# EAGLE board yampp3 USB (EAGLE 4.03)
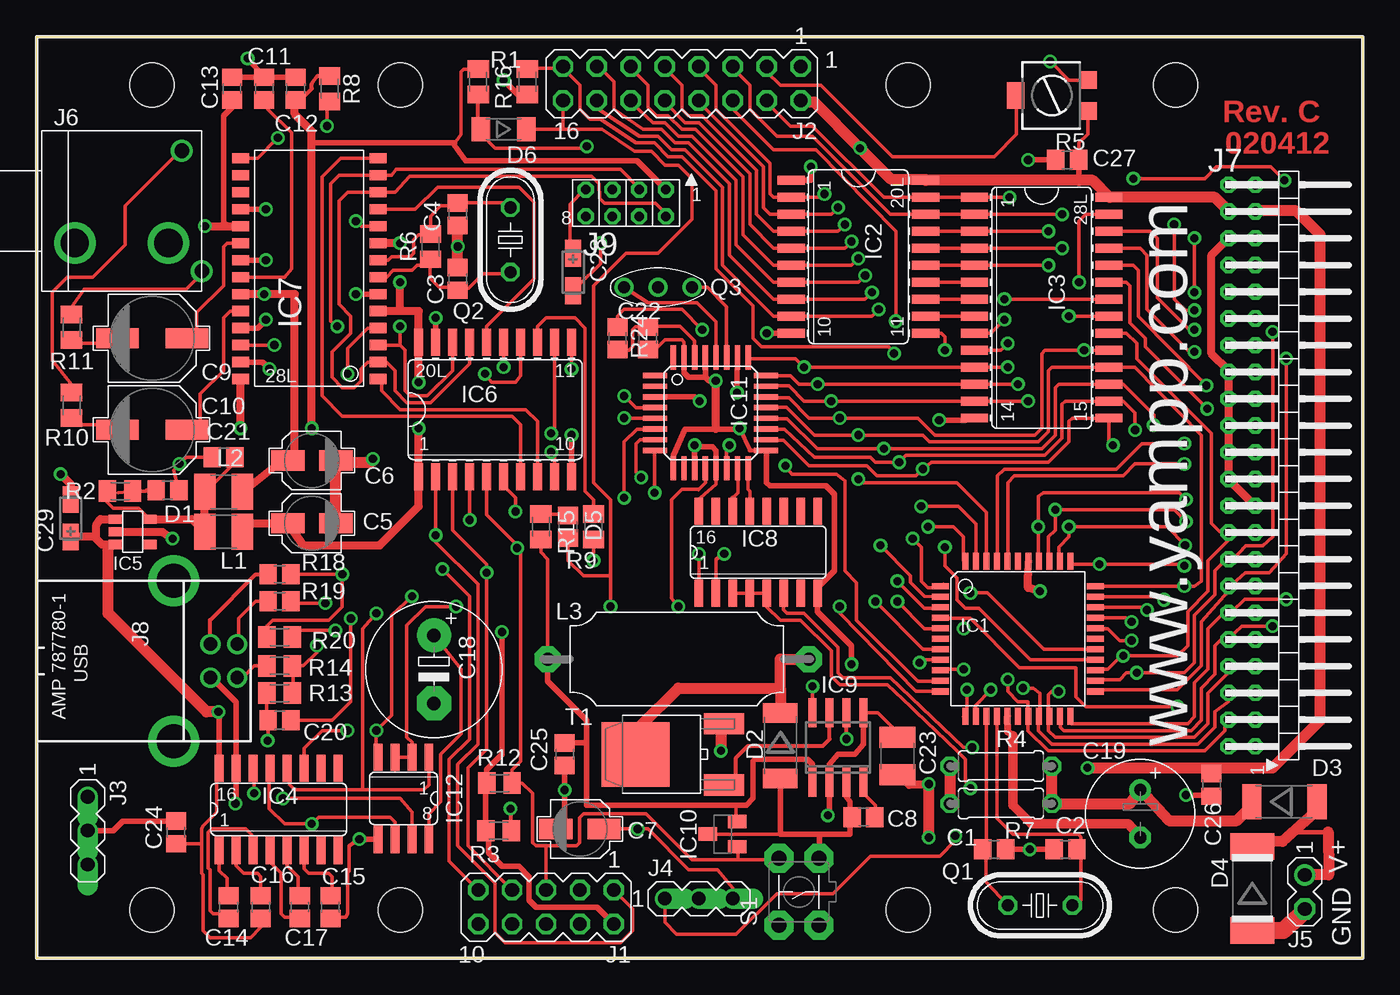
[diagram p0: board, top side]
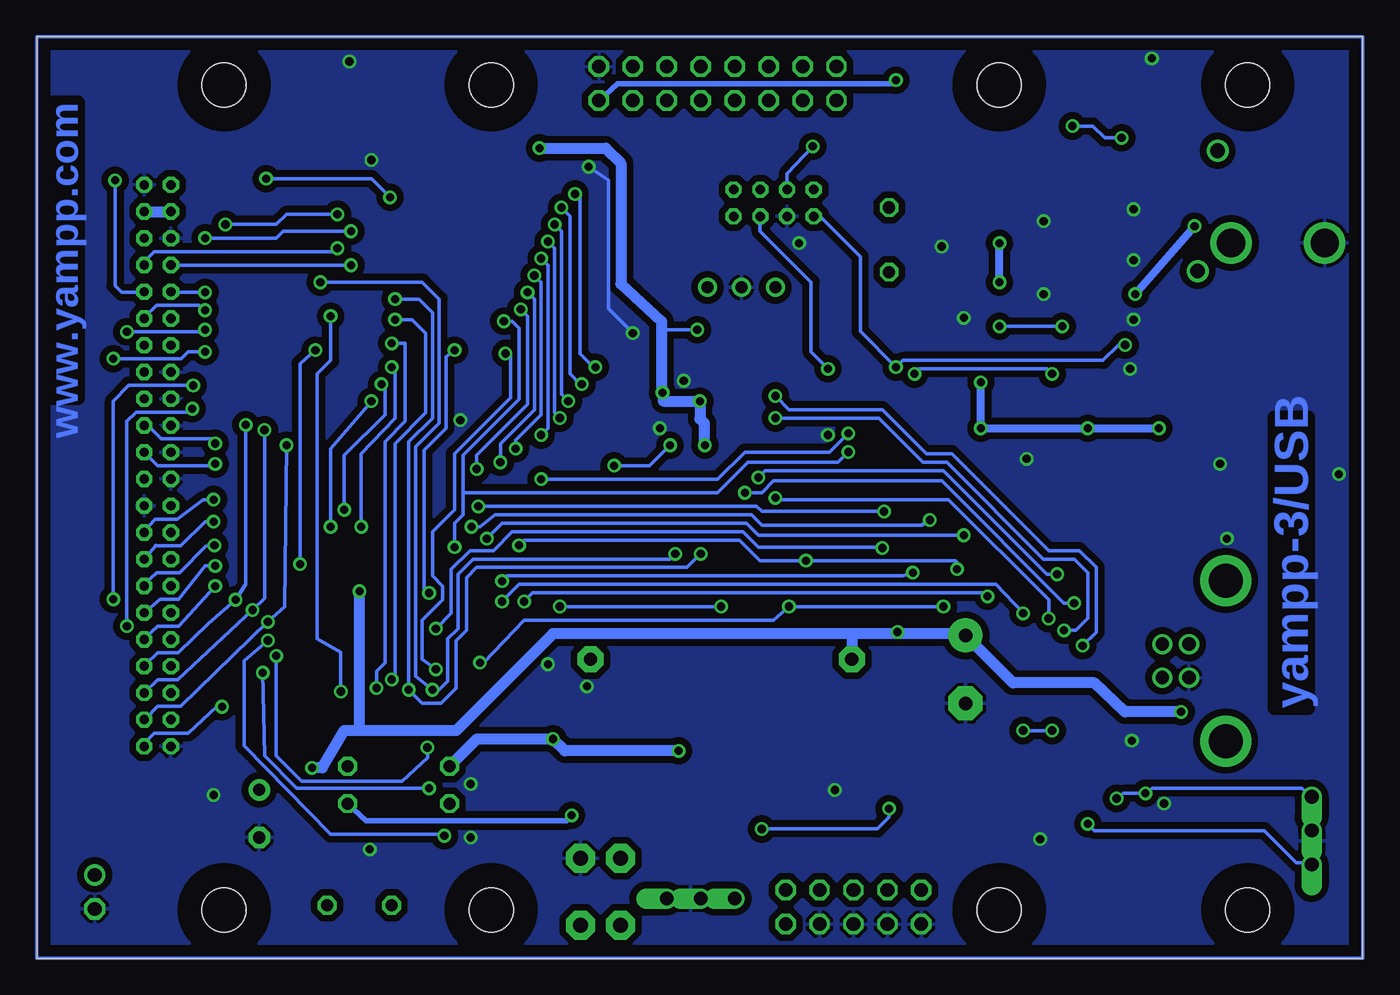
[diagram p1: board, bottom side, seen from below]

Size 99.2 x 68.9 mm. Coordinates in mm from the lower left corner, seen from the top.
Outline: 0,0 0,68.9 99.2,68.9 99.2,0 0,0
Copper layers used: Top, Bottom
Holes 3.3 mm at 85.2,3.6 65.2,3.6 27.2,3.6 8.6,3.6 85.2,65.3 65.2,65.3 27.2,65.3 8.6,65.3
tRestrict: area 6.9,63.6 to 10.3,67; area 25.5,63.6 to 28.9,67; area 63.5,63.6 to 66.9,67; area 83.5,63.6 to 86.9,67; area 83.5,1.9 to 86.9,5.3; area 63.5,1.9 to 66.9,5.3; area 25.5,1.9 to 28.9,5.3; area 6.9,1.9 to 10.3,5.3
bRestrict: area 6.9,63.6 to 10.3,67; area 25.5,63.6 to 28.9,67; area 63.5,63.6 to 66.9,67; area 83.5,63.6 to 86.9,67; area 83.5,1.9 to 86.9,5.3; area 63.5,1.9 to 66.9,5.3; area 25.5,1.9 to 28.9,5.3; area 6.9,1.9 to 10.3,5.3

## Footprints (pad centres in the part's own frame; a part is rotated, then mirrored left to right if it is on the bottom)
C0805 = smd 1.3 x 1.5: 1 -0.85,0; 2 0.85,0
ELNA_RV2_4 = smd 1.5 x 2.5: + 0,1.8; - 0,-1.8
ELNA_RV2_63 = smd 1.5 x 3.2: + 0,2.6; - 0,-2.6
E5-10,5 = drill 1.016 pad 2.54 round: + -2.54,0 | drill 1.016 pad 2.54 octagon: - 2.54,0
E3,5-8 = drill 0.9 pad 1.6 round: + -1.778,0 | drill 0.9 pad 1.6 octagon: - 1.778,0
C3225 = smd 1.6 x 2.7: 1 -1.4,0; 2 1.4,0
CT3216 = smd 2 x 1.2: + -1.4,0; - 1.4,0
LED0805 = smd 1.3 x 1.5: 1 -0.85,0; 2 0.85,0
SOD87 = smd 1.45 x 2.6: A 2.445,0; K -2.445,0
SOD87' = smd 1.45 x 2.6: 1 -2.445,0; 2 2.445,0
SOD15 = smd 2 x 3.3: A 3.145,0; K -3.145,0
SOD80 = smd 1.4 x 1.8: 1 -1.7,0; 2 1.7,0
TQFP44 = smd 1.27 x 0.457: 1 -5.791,3.937; 2 -5.791,3.15; 3 -5.791,2.362; 4 -5.791,1.575; 5 -5.791,0.787; 6 -5.791,0; 7 -5.791,-0.787; 8 -5.791,-1.575; 9 -5.791,-2.362; 10 -5.791,-3.15; 11 -5.791,-3.937; 23 5.791,-3.937; 24 5.791,-3.15; 25 5.791,-2.362; 26 5.791,-1.575; 27 5.791,-0.787; 28 5.791,0; 29 5.791,0.787; 30 5.791,1.575; 31 5.791,2.362; 32 5.791,3.15; 33 5.791,3.937 | smd 0.457 x 1.27: 12 -3.937,-5.791; 13 -3.15,-5.791; 14 -2.362,-5.791; 15 -1.575,-5.791; 16 -0.787,-5.791; 17 0,-5.791; 18 0.787,-5.791; 19 1.575,-5.791; 20 2.362,-5.791; 21 3.15,-5.791; 22 3.937,-5.791; 34 3.937,5.791; 35 3.15,5.791; 36 2.362,5.791; 37 1.575,5.791; 38 0.787,5.791; 39 0,5.791; 40 -0.787,5.791; 41 -1.575,5.791; 42 -2.362,5.791; 43 -3.15,5.791; 44 -3.937,5.791
SO20L = smd 0.66 x 2.032: 1 -5.715,-5.029; 2 -4.445,-5.029; 3 -3.175,-5.029; 4 -1.905,-5.029; 5 -0.635,-5.029; 6 0.635,-5.029; 7 1.905,-5.029; 8 3.175,-5.029; 9 4.445,-5.029; 10 5.715,-5.029; 11 5.715,5.029; 12 4.445,5.029; 13 3.175,5.029; 14 1.905,5.029; 15 0.635,5.029; 16 -0.635,5.029; 17 -1.905,5.029; 18 -3.175,5.029; 19 -4.445,5.029; 20 -5.715,5.029
SO28L = smd 0.66 x 2.032: 1 -8.255,-5.029; 2 -6.985,-5.029; 3 -5.715,-5.029; 4 -4.445,-5.029; 5 -3.175,-5.029; 6 -1.905,-5.029; 7 -0.635,-5.029; 8 0.635,-5.029; 9 1.905,-5.029; 10 3.175,-5.029; 11 4.445,-5.029; 12 5.715,-5.029; 13 6.985,-5.029; 14 8.255,-5.029; 15 8.255,5.029; 16 6.985,5.029; 17 5.715,5.029; 18 4.445,5.029; 19 3.175,5.029; 20 1.905,5.029; 21 0.635,5.029; 22 -0.635,5.029; 23 -1.905,5.029; 24 -3.175,5.029; 25 -4.445,5.029; 26 -5.715,5.029; 27 -6.985,5.029; 28 -8.255,5.029
SO16 = smd 0.66 x 2.032: 1 -4.445,-3.073; 2 -3.175,-3.073; 3 -1.905,-3.073; 4 -0.635,-3.073; 5 0.635,-3.073; 6 1.905,-3.073; 7 3.175,-3.073; 8 4.445,-3.073; 9 4.445,3.073; 10 3.175,3.073; 11 1.905,3.073; 12 0.635,3.073; 13 -0.635,3.073; 14 -1.905,3.073; 15 -3.175,3.073; 16 -4.445,3.073
M5 = smd 0.686 x 0.991: 1 -0.953,-1.283; 2 0,-1.283; 3 0.953,-1.283; 4 0.953,1.308; 5 -0.953,1.308
SOIC-28 = smd 0.762 x 1.27: 1 -7.62,-5.207; 2 -6.35,-5.207; 3 -5.08,-5.207; 4 -3.81,-5.207; 5 -2.54,-5.207; 6 -1.27,-5.207; 7 0,-5.207; 8 1.27,-5.207; 9 2.54,-5.207; 10 3.81,-5.207; 11 5.08,-5.207; 12 6.35,-5.207; 13 7.62,-5.207; 14 8.89,-5.207; 15 8.89,5.08; 16 7.62,5.08; 17 6.35,5.08; 18 5.08,5.08; 19 3.81,5.08; 20 2.54,5.08; 21 1.27,5.08; 22 0,5.08; 23 -1.27,5.08; 24 -2.54,5.08; 25 -3.81,5.08; 26 -5.08,5.08; 27 -6.35,5.08; 28 -7.62,5.08
SO8 = smd 0.6 x 2.2: 1 -1.905,-2.6; 2 -0.635,-2.6; 3 0.635,-2.6; 4 1.905,-2.6; 5 1.905,2.6; 6 0.635,2.6; 7 -0.635,2.6; 8 -1.905,2.6
SOT23 = smd 1 x 1.4: 1 -0.95,-1.1; 2 0.95,-1.1; 3 0,1.1
QFP32 = smd 0.4 x 1.8: 1 -2.8,-4.15; 2 -2,-4.15; 3 -1.2,-4.15; 4 -0.4,-4.15; 5 0.4,-4.15; 6 1.2,-4.15; 7 2,-4.15; 8 2.8,-4.15; 17 2.8,4.15; 18 2,4.15; 19 1.2,4.15; 20 0.4,4.15; 21 -0.4,4.15; 22 -1.2,4.15; 23 -2,4.15; 24 -2.8,4.15 | smd 1.8 x 0.4: 9 4.15,-2.8; 10 4.15,-2; 11 4.15,-1.2; 12 4.15,-0.4; 13 4.15,0.4; 14 4.15,1.2; 15 4.15,2; 16 4.15,2.8; 25 -4.15,2.8; 26 -4.15,2; 27 -4.15,1.2; 28 -4.15,0.4; 29 -4.15,-0.4; 30 -4.15,-1.2; 31 -4.15,-2; 32 -4.15,-2.8
SO08 = smd 0.66 x 2.032: 1 -1.905,-3.073; 2 -0.635,-3.073; 3 0.635,-3.073; 4 1.905,-3.073; 5 1.905,3.073; 6 0.635,3.073; 7 -0.635,3.073; 8 -1.905,3.073
MA05-2 = drill 1.016 octagon: 1 -5.08,-1.27; 2 -5.08,1.27; 3 -2.54,-1.27; 4 -2.54,1.27; 5 0,-1.27; 6 0,1.27; 7 2.54,-1.27; 8 2.54,1.27; 9 5.08,-1.27; 10 5.08,1.27
MA08-2 = drill 1.016 octagon: 1 -8.89,-1.27; 2 -8.89,1.27; 3 -6.35,-1.27; 4 -6.35,1.27; 5 -3.81,-1.27; 6 -3.81,1.27; 7 -1.27,-1.27; 8 -1.27,1.27; 9 1.27,-1.27; 10 1.27,1.27; 11 3.81,-1.27; 12 3.81,1.27; 13 6.35,-1.27; 14 6.35,1.27; 15 8.89,-1.27; 16 8.89,1.27
MA03-1 = drill 1.016 offset: 1 -2.54,0; 2 0,0; 3 2.54,0
MA02-1 = drill 1.016 pad 1.6 round: 1 -1.27,0 | drill 1.016 pad 1.6 octagon: 2 1.27,0
JACKSW = drill 2.1 round: 1 2.4,-3.5; 3 2.4,3.5 | drill 1.1 round: 2 4.5,6; 4 -4.5,4.5
CON40L-2W = drill 0.7 pad 1.118 octagon: 1 21,1; 2 21,-1; 3 19,1; 4 19,-1; 5 17,1; 6 17,-1; 7 15,1; 8 15,-1; 9 13,1; 10 13,-1; 11 11,1; 12 11,-1; 13 9,1; 14 9,-1; 15 7,1; 16 7,-1; 17 5,1; 18 5,-1; 19 3,1; 20 3,-1; 21 1,1; 22 1,-1; 23 -1,1; 24 -1,-1; 25 -3,1; 26 -3,-1; 27 -5,1; 28 -5,-1; 29 -7,1; 30 -7,-1; 31 -9,1; 32 -9,-1; 33 -11,1; 34 -11,-1; 35 -13,1; 36 -13,-1; 37 -15,1; 38 -15,-1; 39 -17,1; 40 -17,-1; 41 -19,1; 42 -19,-1; 43 -21,1; 44 -21,-1
USB-B = drill 1 round: 1 1.25,14.99; 2 -1.25,14.99; 3 -1.25,12.99; 4 1.25,12.99 | drill 2.54 pad 3.81 round: P$1 -6,10.25; P$2 6,10.25
CON8-2 = drill 0.7 pad 1.118 octagon: 1 3,0.98; 2 3,-1.02; 3 1,0.98; 4 1,-1.02; 5 -1,0.98; 6 -1,-1.02; 7 -3,0.98; 8 -3,-1.02
L1210 = smd 1.6 x 2.7: 1 -1.4,0; 2 1.4,0
HM50 = drill 1 pad 1.93 octagon: P$1 -9.89,0; P$2 9.66,0
HC49U-V = drill 0.9 octagon: 1 -2.413,0; 2 2.413,0
MURATA_CST = drill 0.9 round: 1 -2.54,0; 2 0,0; 3 2.54,0
M0805 = smd 1.3 x 1.6: 1 -0.95,0; 2 0.95,0
0207/7 = drill 0.9 octagon: 1 -3.81,0; 2 3.81,0
23B = smd 1.3 x 1.3: 1 -1.15,-2.7; 3 1.15,-2.7 | smd 2 x 1.3: 2 0,2.7
R0805 = smd 1.3 x 1.5: 1 -0.85,0; 2 0.85,0
ALPS_45 = drill 1.118 pad 2.159 octagon: 1 -2.49,1.5; 2 2.51,1.5; 3 -2.49,-1.5; 4 2.51,-1.5
DPAK_369A_2 = smd 5.08 x 4.826: D -3.861,0 | smd 2.997 x 1.6: G 2.769,-2.286; S 2.769,2.286

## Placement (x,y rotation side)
C1  33pF  [C0805]  71.63,8.13 0 top
C2  33pF  [C0805]  76.96,8.13 180 top
C3  33pF  [C0805]  31.5,50.8 270 top
C4  33pF  [C0805]  31.5,55.63 90 top
C5  10uF/16  [ELNA_RV2_4]  20.57,32.51 90 top
C6  10uF/16  [ELNA_RV2_4]  20.57,37.21 90 top
C7  10uF/16  [ELNA_RV2_4]  40.64,9.65 270 top
C8  100nF  [C0805]  61.85,10.54 0 top
C9  100uF/10  [ELNA_RV2_63]  8.64,46.35 270 top
C10  100uF/10  [ELNA_RV2_63]  8.64,39.5 270 top
C11  100nF  [C0805]  17.02,65.02 90 top
C12  100nF  [C0805]  19.37,65.02 90 top
C13  100nF  [C0805]  14.61,65.02 90 top
C14  100nF  [C0805]  16.76,3.81 90 top
C15  100nF  [C0805]  21.97,3.81 270 top
C16  100nF  [C0805]  14.35,3.81 270 top
C17  100nF  [C0805]  19.68,3.81 90 top
C18  220uF  [E5-10,5]  29.72,21.59 270 top
C19  47uF  [E3,5-8]  82.55,10.79 270 top
C20  100nF  [C0805]  18.16,17.78 0 top
C21  100nF  [C0805]  13.97,37.47 0 top
C22  100nF  [C0805]  45.72,46.35 90 top
C23  470nF  [C3225]  64.39,15.11 90 top
C24  100nF  [C0805]  10.41,9.4 270 top
C25  100nF  [C0805]  39.5,15.24 90 top
C26  100nF  [C0805]  87.88,12.95 90 top
C27  100nF  [C0805]  77.09,59.69 0 top
C28  1uF/16  [CT3216]  40.13,51.31 270 top
C29  1uF/16  [CT3216]  2.54,32.89 90 top
D1  [LED0805]  9.78,34.99 0 top
D2  PRLL5818  [SOD87]  55.63,15.88 270 top
D3  LL4004  [SOD87']  93.34,11.68 0 top
D4  SM15T15A  [SOD15]  90.93,5.21 270 top
D5  [LED0805]  39.75,32.26 270 top
D6  BAS32  [SOD80]  34.92,61.98 180 top
IC1  ATmega161  [TQFP44]  73.41,23.88 0 top
IC2  74HC573  [SO20L]  61.47,52.45 270 top
IC3  62256  [SO28L]  75.18,48.64 270 top
IC4  MAX202CSE  [SO16]  18.1,11.11 0 top
IC5  LP2980  [M5]  7.18,31.88 270 top
IC6  74LVC245  [SO20L]  34.29,41.02 0 top
IC7  VS1001  [SOIC-28]  20.32,50.93 90 top
IC8  74HC138D  [SO16]  53.98,30.35 0 top
IC9  MAX1626ESA  [SO8]  59.94,15.75 0 top
IC10  DS1813R  [SOT23]  51.31,9.27 90 top
IC11  FT8U245BM  [QFP32]  50.42,40.77 270 top
IC12  MAX481CSA  [SO08]  27.43,11.94 180 top
J1  PROG  [MA05-2]  38.1,3.81 180 top
J2  DISPLAY  [MA08-2]  48.26,65.41 180 top
J3  RS-232  [MA03-1]  3.81,9.53 270 top
J4  IR  [MA03-1]  49.53,4.45 0 top
J5  POWER  [MA02-1]  94.87,4.95 270 top
J6  Headphones  [JACKSW]  6.35,55.88 270 top
J7  ATA_IF  [CON40L-2W]  90.17,36.83 270 top
J8  USB  [USB-B]  0,22.23 270 top
J9  NOKIA LCD  [CON8-2]  44.07,56.49 0 top
L1  10u  [L1210]  13.97,31.88 0 top
L2  10u  [L1210]  13.97,34.86 0 top
L3  22uH  [HM50]  47.88,22.35 180 top
Q1  7.3728 MHz  [HC49U-V]  75.06,3.94 180 top
Q2  12.288 MHz  [HC49U-V]  35.43,53.72 90 top
Q3  6MHz  [MURATA_CST]  46.48,50.16 180 top
R1  10k  [M0805]  36.7,65.53 270 top
R2  470  [M0805]  6.22,34.92 180 top
R3  47  [M0805]  34.54,9.53 180 top
R4  0.1R  [0207/7]  72.14,14.35 0 top
R5  5k  [23B]  75.95,64.52 90 top
R6  1M  [M0805]  29.46,53.21 90 top
R7  0.1R  [0207/7]  72.14,11.56 0 top
R8  10k  [M0805]  21.91,65.02 270 top
R9  4k7  [M0805]  41.66,32.26 90 top
R10  15  [M0805]  2.6,41.34 90 top
R11  15  [M0805]  2.6,47.18 90 top
R12  10k  [M0805]  34.61,13.08 180 top
R13  10k  [M0805]  18.16,19.81 0 top
R14  4k7  [M0805]  18.16,21.84 180 top
R15  1k  [M0805]  37.72,32.26 270 top
R16  4k7  [M0805]  33.02,65.53 270 top
R18  27  [R0805]  18.16,28.7 180 top
R19  27  [R0805]  18.16,26.67 180 top
R20  1k5  [M0805]  18.16,24 180 top
R24  470  [R0805]  43.43,46.35 90 top
S1  RESET  [ALPS_45]  57.02,4.95 90 top
T1  MTD20P03HDL  [DPAK_369A_2]  48.64,15.24 0 top

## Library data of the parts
C1-C4 C8 C11-C29 L1 L2 R1-R4 R6-R16 R18-R20 R24 = rcl
C5-C7 C9 C10 D2 D4 IC9 IC11 J6 L3 Q3 R5 T1 = jesper
D1 D5 = led
D3 D6 = semicon-smd-ipc
IC1 = atmel
IC2 IC3 = 74XXSMD
IC4 IC12 = maxim
IC5 = LP2980
IC6 = 74XX
IC7 = VLSI
IC8 = 74xx-us
IC10 = dallas
J1-J4 = CON-LSTB
J5 = CON-LSTB@2
J7 J9 = ribcon2
J8 = con-amp
Q1 Q2 = crystal
S1 = key

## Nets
/DIOR: IC1.41 J7.25
/DIOW: IC1.40 J7.23
A0: IC2.19 IC3.1 J2.4 J7.35
A1: IC2.18 IC3.2 J2.5 J7.33
A2: IC2.17 IC3.3 J7.36
A3: IC2.16 IC3.4 J7.37
A4: IC2.15 IC3.5 J7.38
A5: IC2.14 IC3.6
A6: IC2.13 IC3.7
A7: IC2.12 IC3.8
A8: IC1.18 IC3.9 J7.4
A9: IC1.19 IC3.10 J7.6
A10: IC1.20 IC3.21 J7.8
A11: IC1.21 IC3.23 J7.10
A12: IC1.22 IC3.24 J7.12
A13: IC1.23 IC3.25 J7.14
A14: IC1.24 IC3.26 IC8.3 IC8.4 IC8.5 J7.16
A15: IC1.25 IC3.20 IC8.6 J7.18
AD0: IC1.37 IC2.2 IC3.11 IC11.25 J2.7 J7.17
AD1: IC1.36 IC2.3 IC3.12 IC11.24 J2.8 J7.15
AD2: IC1.35 IC2.4 IC3.13 IC11.23 J2.9 J7.13
AD3: IC1.34 IC2.5 IC3.19 IC11.22 J2.10 J7.11
AD4: IC1.33 IC2.6 IC3.18 IC11.21 J2.11 J7.9
AD5: IC1.32 IC2.7 IC3.17 IC11.20 J2.12 J7.7
AD6: IC1.31 IC2.8 IC3.16 IC11.19 J2.13 J7.5
AD7: IC1.30 IC2.9 IC3.15 IC11.18 J2.14 J7.3
ALE: IC1.27 IC2.11
BSYNC: IC1.43 IC6.6
DC_IN: D3.2 D4.K J5.1
DREQ: IC1.42 IC6.12
GND: C1.2 C2.2 C3.1 C4.1 C5.- C6.- C7.- C8.1 C11.2 C12.2 C13.2 C15.2 C18.- C19.- C20.1 C21.1 C22.1 C23.1 C24.1 C25.1 C26.1 C27.1 C28.- C29.- D1.2 D2.A D4.A IC1.16 IC2.1 IC2.10 IC3.14 IC4.15 IC5.2 IC6.10 IC6.19 IC7.6 IC7.10 IC7.18 IC7.21 IC7.25 IC7.27 IC8.8 IC9.3 IC9.8 IC10.3 IC11.9 IC11.17 IC11.29 IC11.31 IC12.5 J1.4 J1.6 J1.8 J1.10 J2.1 J3.2 J4.2 J5.2 J6.1 J7.2 J7.19 J7.22 J7.24 J7.26 J7.28 J7.30 J7.40 J7.43 J8.4 J9.6 Q3.2 R5.3 R13.1 S1.4
IR_IN: IC1.29 J4.1
KEYS: IC1.9 J2.15 R1.1
LCD_E: IC1.26 IC6.9 J2.6
LCD_E3: IC6.11 J9.4
LCD_NEG: C15.1 IC4.6
MISO: IC1.2 J1.9 R9.1
MOSI: IC1.1 IC6.2 J1.1
MOSI3: IC6.18 IC7.3 IC7.13 J9.3
MP3: IC1.44 IC6.4
N$1: IC7.15 R8.2
N$2: C11.1 IC7.22
N$3: C10.+ IC7.24
N$4: C9.+ IC7.20
N$5: D1.1 R2.1
N$6: D2.K L3.P$1 T1.D
N$7: C1.1 IC1.14 Q1.2
N$8: J6.2 R11.2
N$9: C9.- R11.1
N$10: C2.1 IC1.15 Q1.1
N$12: IC4.14 IC12.7 J3.1
N$13: C4.2 IC7.8 Q2.2 R6.2
N$14: C3.2 IC7.7 Q2.1 R6.1
N$16: IC4.13 IC12.6 J3.3
N$17: IC6.13 R9.2
N$18: C16.2 IC4.3
N$19: C10.- R10.1
N$20: C17.2 IC4.5
N$21: C17.1 IC4.4
N$22: C14.2 IC4.2
N$23: J6.4 R10.2
N$24: IC8.13 IC11.16
N$25: IC8.14 IC11.15
N$26: IC9.7 T1.G
N$27: J8.3 R18.2
N$28: IC9.6 R4.1 R7.1 T1.S
N$29: C19.+ C23.2 D3.1 IC9.2 IC9.5 R4.2 R7.2
N$30: IC11.4 R13.2 R14.1
N$31: IC11.7 R18.1 R20.2
N$34: J8.1 R14.2
N$35: IC6.16 IC7.11
N$36: C21.2 IC5.5 L1.1 L2.1 R2.2
N$37: IC6.14 IC7.4
N$38: IC6.7 IC7.14
N$39: IC6.8 IC7.1
N$40: IC11.8 R19.1
N$41: C8.2 IC9.4
N$42: C20.2 IC11.6
N$43: IC11.5 R20.1
N$44: J8.2 R19.2
N$45: C22.2 IC11.30 R24.1
N$49: C16.1 IC4.1
N$50: D5.1 R15.1
N$53: C7.+ J4.3 R3.1
N$54: IC11.27 Q3.1
N$55: IC11.28 Q3.3
RD: IC1.13 IC3.22 IC8.1
RST: IC1.4 IC6.5 IC10.1 J1.5 J7.1 R12.1 S1.2
RST3: IC6.15 IC7.26 J9.8
RX: IC1.5 IC4.12 IC12.1
RXF: IC1.11 IC11.12
SCF: D6.2 J9.5 R16.2
SCK: IC1.3 IC6.3 J1.7
SCK3: IC6.17 IC7.2 IC7.12 J9.2
TX: IC1.7 IC4.11 IC12.4
TX_ENABLE: D5.2 D6.1 IC1.8 IC12.2 IC12.3 J2.16
TXE: IC1.10 IC11.14
VCC: C14.1 C18.+ C24.2 C25.2 C26.2 C27.2 C29.+ IC1.38 IC2.20 IC3.28 IC4.16 IC5.1 IC5.3 IC8.16 IC9.1 IC10.2 IC11.3 IC11.11 IC11.13 IC11.26 IC12.8 J1.2 J2.2 J7.41 J7.42 L3.P$2 R1.2 R3.2 R5.1 R12.2 R15.2 R24.2
VCC/2 [power]: C6.+ C13.1 IC7.19 IC7.23 L2.2
VDD: C5.+ C12.1 IC6.1 IC6.20 IC7.5 IC7.9 IC7.28 J9.1 L1.2 R8.1 R16.1
VO: J2.3 R5.2
VOUT: C28.+ J9.7
WR: IC1.12 IC3.27 IC8.2

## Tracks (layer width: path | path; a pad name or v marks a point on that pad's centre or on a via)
/DIOR  (via drill 0.61)
  Top 0.254: v85.85,38.48 82.68,38.48 80.77,36.58 72.39,36.58 71.88,36.07 71.88,29.72 IC1.41
  Bottom 0.254: J7.25 90.88,39.83 89.89,38.84 86.08,38.84 86.11,38.73 v85.85,38.48
/DIOW  (via drill 0.61)
  Top 0.254: v85.85,36.96 82.17,36.96 81.28,36.07 73.15,36.07 72.64,35.56 72.64,29.72 72.62,29.69 IC1.40
  Bottom 0.254: J7.23 90.17,36.83 85.98,36.83 v85.85,36.96
A0  (via drill 0.61)
  Top 0.254: J2.4 54.61,64.01 56.39,62.23 58.04,62.23 63.37,56.9 IC2.19 IC3.1 v72.77,56.9 | v82.04,58.29 87.38,58.29 88.27,59.18 92.33,59.18 v93.34,58.17
  Bottom 0.254: v72.77,56.9 74.17,58.29 v82.04,58.29 | v93.34,58.17 93.34,50.29 92.84,49.78 | 92.84,49.78 91.19,49.81 J7.35 | 92.84,49.78 90.93,49.78
A1  (via drill 0.61)
  Top 0.254: 66.55,55.63 66.5,55.42 IC2.18 | 66.55,55.63 IC3.2 v76.71,55.63 | IC2.18 66.55,55.63 | IC2.18 63.88,55.63 58.04,61.47 55.37,61.47 53.34,63.5 53.34,65.28 52.07,66.55 J2.5 | v85.09,54.86 85.09,49.28 85.92,48.45 v86.61,48.45
  Bottom 0.254: v76.71,55.63 80.52,55.63 81.28,54.86 v85.09,54.86 | J7.33 91.17,47.77 91.19,47.75 91.19,47.88 90.23,48.83 87.06,48.83 v86.61,48.45
A2  (via drill 0.61)
  Top 0.254: IC2.17 IC3.3 v75.69,54.36 | v86.61,53.85 v86.61,49.78
  Bottom 0.254: v75.69,54.36 80.77,54.36 81.28,53.85 v86.61,53.85 | J7.36 89.17,49.8 89.15,49.78 v86.61,49.78
A3  (via drill 0.61)
  Top 0.254: 66.29,53.09 IC2.16 70.1,53.09 | 70.1,53.09 IC3.4 | 70.1,53.09 v76.71,53.09
  Bottom 0.254: J7.37 91.17,52.09 90.42,52.83 76.96,52.83 v76.71,53.09
A4  (via drill 0.61)
  Top 0.254: IC2.15 IC3.5 v75.69,51.82
  Bottom 0.254: J7.38 89.15,51.82 v75.69,51.82
A5
  Top 0.254: IC2.14 IC3.6
A6
  Top 0.254: IC2.13 IC3.7
A7
  Top 0.254: IC2.12 IC3.8
A8  (via drill 0.61)
  Top 0.254: 74.17,18.03 74.17,17.02 75.69,15.49 87.38,15.49 88.9,17.02 88.9,17.27 89,17.48 J7.4 | 74.17,18.03 74.17,18.06 IC1.18 74.19,18.06 74.17,18.03 | IC3.9 71.37,46.74 v72.39,47.75 | 74.17,18.03 74.17,19.18 73.41,19.18 72.64,19.94 v72.64,20.83
  Bottom 0.254: v72.39,47.75 71.12,47.75 70.1,46.74 70.1,40.77 72.39,38.48 72.39,21.08 v72.64,20.83
A9  (via drill 0.61)
  Top 0.254: IC3.10 72.14,45.47 v72.64,45.97 | v73.79,20.19 74.55,20.19 75.06,19.81 75.06,18.54 74.93,18.29 74.98,18.24 IC1.19 74.93,18.03 74.93,17.02 75.95,16 86.87,16 88.14,17.27 88.14,18.41 89.15,19.18 89.15,19.76 89.15,19.81 J7.6
  Bottom 0.254: v72.64,45.97 71.63,45.97 71.63,40.13 73.15,38.61 73.15,22.1 73.79,21.46 v73.79,20.19
A10  (via drill 0.61)
  Top 0.254: J7.8 89.16,21.84 89.15,21.34 87.63,19.81 87.63,17.53 86.61,16.51 76.2,16.51 75.69,17.02 75.69,18.01 IC1.20 75.69,18.16 75.69,19.68 75.95,19.94 v76.45,19.94 | 80.26,48.01 IC3.21 v77.22,48.01
  Bottom 0.254: v76.45,19.94 76.45,22.86 78.23,23.88 78.23,43.69 77.22,44.7 v77.22,48.01
A11  (via drill 0.61)
  Top 0.254: IC1.21 76.58,17.93 76.58,17.27 76.83,17.02 86.36,17.02 87.12,17.78 87.12,20.19 88.14,21.21 88.14,23.37 88.65,23.88 89.15,23.88 | 89.15,23.88 89.15,23.85 J7.10 | 89.15,23.88 90.17,24.83 v92.46,24.83 | IC3.23 81.53,50.55 81.79,50.29 81.79,47.5 82.93,46.35 82.93,45.72 v87.57,41.08
  Bottom 0.254: v92.46,24.83 92.46,40.13 91.76,40.83 87.95,40.83 v87.57,41.08
A12  (via drill 0.61)
  Top 0.254: IC1.22 77.39,17.53 86.11,17.53 86.61,18.03 86.61,20.57 87.63,21.59 87.63,24.64 88.9,25.91 | J7.12 89.15,25.85 89.15,25.91 88.9,25.91 | 88.9,25.91 89.41,25.91 90.4,26.84 v93.47,26.84 | IC3.24 82.04,51.82 82.42,51.44 82.42,48.01 v87.5,42.82
  Bottom 0.254: v93.47,26.84 93.47,41.66 92.33,42.85 v87.5,42.82
A13  (via drill 0.61)
  Top 0.254: IC1.23 79.32,20.07 85.34,20.07 87.12,21.84 87.12,25.15 89.15,27.43 89.15,27.69 | 89.3,27.83 J7.14 89.15,27.81 89.15,27.69 | IC3.25 82.55,53.09 83.06,52.58 83.06,48.51 86.23,45.34 v86.61,45.34 | v93.47,44.83 93.47,30.23 92.2,28.83 90.42,28.83 89.15,27.69
  Bottom 0.254: v86.61,45.34 87.88,45.34 88.39,44.83 v93.47,44.83
A14  (via drill 0.61)
  Top 0.254: IC1.24 79.3,20.83 81.03,20.83 81.53,21.34 v82.3,21.34 85.85,21.34 86.61,22.1 86.61,25.65 88.14,27.18 88.14,28.96 88.9,29.72 | J7.16 89.15,29.81 89.15,29.72 88.9,29.72 | 88.9,29.72 89.41,29.72 90.45,30.82 91.72,30.82 92.46,31.5 v92.46,46.84 | IC3.26 83.31,54.36 83.82,53.85 83.82,49.4 86.23,46.99 v86.61,46.99 | IC8.3 IC8.4 | IC8.4 53.31,27.66 53.34,27.69 | IC8.4 54.59,27.28 | 54.59,27.28 IC8.5 54.61,26.29 55.63,25.27 57.15,25.27 59.44,22.99 59.44,21.08 60.07,20.45 63.63,20.45 65.41,18.8 65.79,18.41 68.83,15.49 69.47,14.86 69.47,13.21 v69.85,12.7 | 54.59,27.28 54.61,27.69
  Bottom 0.254: v86.61,46.99 87,46.84 v92.46,46.84 | v69.85,12.7 79.76,12.7 82.17,15.11 v82.3,21.34
A15  (via drill 0.61)
  Top 0.254: IC1.25 79.27,21.59 80.14,21.59 81.15,22.61 v81.28,22.61 85.34,22.61 86.11,23.37 86.11,25.91 87.63,27.43 87.63,29.72 89.15,31.24 89.15,31.75 | 89.15,31.85 89.15,32 | 89.15,31.85 J7.18 | IC3.20 81.53,46.74 82.3,45.97 82.3,44.83 87.88,39.24 87.88,32.51 88.52,31.88 89.03,31.88 89.15,31.75 | 89.15,31.75 89.15,31.85 | IC8.6 55.88,26.04 56.13,25.78 57.4,25.78 59.94,23.24 59.94,21.34 60.33,20.95 63.88,20.95 69.34,15.75 v69.98,15.75
  Bottom 0.254: v69.98,15.75 69.98,14.99 71.88,13.21 79.38,13.21 81.28,15.11 v81.28,22.61
AD0  (via drill 0.61)
  Top 0.254: J2.7 49.53,66.55 50.8,65.28 50.8,63.5 54.86,59.44 54.86,57.15 55.12,56.9 IC2.2 58.55,56.9 v58.93,57.15 | v72.64,44.2 IC3.11 v57.4,44.2 56.77,44.83 53.21,44.83 53.2,44.97 53.2,44.96 53.22,44.96 IC11.25 | IC1.37 74.93,29.72 v74.93,32.26 74.93,34.54 75.31,34.8 85.47,34.8 v85.98,34.29
  Bottom 0.254: v58.93,57.15 58.8,57.15 58.55,56.9 58.55,45.21 57.53,44.2 v57.4,44.2 | v72.64,44.2 72.39,43.94 72.39,40.39 74.93,37.72 v74.93,32.26 | J7.17 91.17,31.86 91.19,31.88 90.36,32.83 88.71,32.83 86.74,34.29 v85.98,34.29
AD1  (via drill 0.61)
  Top 0.254: J2.8 49.53,64.01 54.36,59.18 54.36,56.13 54.86,55.63 IC2.3 59.44,55.63 v59.94,56.13 | 54.61,43.56 54.62,43.57 | 54.61,43.56 56.39,43.56 57.02,42.93 v58.42,42.93 IC3.12 v73.41,42.93 | IC1.36 75.72,29.72 75.69,29.72 75.69,31.5 76.2,32 v76.2,33.53 85.09,33.53 v85.98,32.64 | IC11.24 54.48,43.57 54.48,43.56 54.61,43.56
  Bottom 0.254: v59.94,56.13 59.31,55.5 59.31,43.69 58.55,42.93 v58.42,42.93 | v73.41,42.93 73.15,42.67 73.15,40.64 76.2,37.59 v76.2,33.53 | 90.29,30.84 J7.15 | v85.98,32.64 86.61,32.64 88.42,30.84 90.29,30.84 | 90.29,30.84 90.3,30.86
AD2  (via drill 0.61)
  Top 0.254: J2.9 46.99,66.55 48.26,65.28 48.26,63.5 48.77,62.99 49.78,62.99 53.85,58.93 53.85,55.63 55.12,54.36 IC2.4 59.94,54.36 v60.45,54.86 | 54.86,42.8 54.83,42.77 | 54.86,42.8 56.26,42.8 57.4,41.66 v59.44,41.66 IC3.13 v74.17,41.66 | IC1.35 76.5,29.72 76.45,29.72 76.45,30.73 77.22,31.5 v77.22,32.26 84.58,32.26 v85.92,30.86 | IC11.23 54.61,42.77 54.61,42.8 54.86,42.8
  Bottom 0.254: v60.45,54.86 59.94,54.36 59.94,42.16 v59.44,41.66 | v74.17,41.66 77.22,38.1 v77.22,32.26 | J7.13 91.17,27.96 90.23,28.83 88.52,28.83 86.55,30.8 v85.92,30.86
AD3  (via drill 0.61)
  Top 0.254: J2.10 46.99,64.01 48.51,62.48 49.53,62.48 53.34,58.67 53.34,54.86 55.12,53.09 IC2.5 60.45,53.09 v60.96,53.59 | IC3.19 v78.36,45.47 75.44,45.47 75.18,45.21 75.18,39.62 74.68,39.12 67.18,39.12 65.91,40.39 v60.07,40.39 57.78,40.39 56.26,41.91 54.99,41.91 54.86,42.04 54.86,41.97 54.68,41.97 54.61,41.97 | 77.27,29.67 77.22,29.72 | 77.27,29.67 IC1.34 | v85.85,29.34 85.6,29.46 v79.5,29.46 77.47,29.46 77.27,29.67 | IC11.22 54.61,41.97 | 54.61,41.97 54.61,42.04
  Bottom 0.254: v60.96,53.59 60.45,53.09 60.45,40.77 v60.07,40.39 | v78.36,45.47 79.5,44.45 v79.5,29.46 | J7.11 89.96,26.84 88.59,26.84 86.61,29.34 v85.85,29.34
AD4  (via drill 0.61)
  Top 0.254: J2.11 44.45,66.55 45.72,65.28 45.72,63.63 46.35,62.99 47.24,62.99 48.26,61.98 49.28,61.98 52.83,58.42 52.83,54.1 55.12,51.82 IC2.6 60.96,51.82 v61.47,52.32 | IC1.33 v85.85,27.81 86.61,27.81 87.12,28.19 87.12,39.12 82.17,44.2 IC3.18 75.95,44.2 75.69,43.94 75.69,39.37 74.93,38.61 66.8,38.61 66.29,39.12 v61.47,39.12 58.17,39.12 56.07,41.21 54.86,41.21 54.76,41.17 54.61,41.17 | IC11.21 54.61,41.17 | 54.61,41.17 54.61,41.15
  Bottom 0.254: 91.06,24 90.17,24.83 88.58,24.83 v85.85,27.81 | 91.06,24 91.19,23.88 | v61.47,52.32 60.96,51.82 60.96,39.62 v61.47,39.12 | J7.9 91.03,23.98 91.06,24
AD5  (via drill 0.61)
  Top 0.254: J2.12 44.45,64.01 46.1,62.48 46.99,62.48 48.01,61.47 49.02,61.47 52.32,58.17 52.32,53.34 55.12,50.55 IC2.7 61.47,50.55 v61.98,51.05 | IC1.32 83.72,27.03 v84.33,26.8 | v83.57,39.88 83.57,40.64 81.28,42.93 IC3.17 76.45,42.93 76.2,42.67 76.2,39.12 75.18,38.1 v63.37,38.1 58.42,38.1 56.13,40.32 54.61,40.32 54.62,40.4 54.48,40.4 54.48,40.37 IC11.20
  Bottom 0.254: 91.06,21.97 90.14,22.84 88.62,22.84 86.36,25.02 v84.33,26.8 83.57,27.94 v83.57,39.88 | 91.06,21.97 91.19,21.84 | v61.98,51.05 61.47,50.55 61.47,40.64 63.37,38.73 v63.37,38.1 | J7.7 91.03,21.95 91.06,21.97
AD6  (via drill 0.61)
  Top 0.254: J2.13 41.91,66.8 43.18,65.53 43.18,63.5 45.34,61.98 46.74,61.98 47.75,60.96 48.77,60.96 51.82,57.91 51.82,52.58 55.12,49.28 IC2.8 61.98,49.28 v62.48,49.78 | IC1.31 82.6,26.24 v83.06,26.04 | 54.55,39.56 54.62,39.51 | 54.55,39.56 55.94,39.56 58.17,37.47 62.36,37.47 62.74,37.08 v64.52,37.08 65.02,37.59 75.44,37.59 76.71,38.86 76.71,41.4 76.96,41.66 IC3.16 81.28,41.66 82.17,40.77 v82.17,39.5 | 54.61,39.57 54.61,39.56 54.55,39.56 | IC11.19 54.61,39.57 | 54.61,39.57 54.61,39.62
  Bottom 0.254: J7.5 91.19,19.81 | J7.5 | J7.5 90.17,20.83 88.65,20.83 v83.06,26.04 82.17,26.92 v82.17,39.5 | v62.48,49.78 61.98,49.28 61.98,41.02 64.52,38.48 v64.52,37.08
AD7  (via drill 0.61)
  Top 0.254: J2.14 41.91,64.01 42.04,63.88 42.04,63.5 45.09,61.47 46.48,61.47 47.5,60.45 48.51,60.45 51.31,57.66 51.31,51.82 55.12,48.01 IC2.9 62.48,48.01 v62.99,48.51 | IC1.30 81.48,25.45 v81.92,25.15 | 54.62,38.74 54.61,38.73 54.74,38.73 | 54.74,38.73 55.88,38.73 57.78,36.83 62.1,36.83 62.87,36.07 65.79,36.07 v66.29,36.58 66.93,37.08 75.69,37.08 77.22,38.61 77.22,40.13 77.47,40.39 IC3.15 80.21,38.66 v80.52,38.35 | IC11.18 54.74,38.77 54.74,38.73
  Bottom 0.254: 91.06,17.91 90.14,18.83 88.49,18.83 88.44,18.85 v81.92,25.15 80.64,26.29 v80.52,38.35 | 91.06,17.91 91.19,17.78 | v62.99,48.51 62.48,48.01 62.48,41.4 66.29,37.59 v66.29,36.58 | J7.3 91.03,17.88 91.06,17.91
ALE  (via drill 0.61)
  Top 0.254: IC1.27 75.34,23.09 71.12,27.3 v69.85,27.3 | IC2.11 67.69,46.74 67.94,46.48 v67.94,45.47
  Bottom 0.254: v69.85,27.3 70.23,27.56 70.23,37.97 68.58,39.62 68.58,44.96 v67.94,45.47
BSYNC  (via drill 0.61)
  Top 0.254: IC1.43 70.26,32.49 68.96,33.78 v66.17,33.78 | v35.81,33.4 35.81,34.42 34.92,35.31 IC6.6
  Bottom 0.254: v66.17,33.78 45.34,33.78 44.96,33.4 v35.81,33.4
DC_IN
  Top 0.356: 93.19,8.73 93.98,9.4 96.62,9.43
  Top 0.813: D3.2 95.76,11.68 95.76,11.81 95.63,11.94 | D4.K 90.93,8.64 91.19,8.76 93.19,8.73 95.63,10.92 95.63,11.94 | 95.63,11.94 95.76,12.06 | 96.62,9.43 96.65,6.22 J5.1
DREQ  (via drill 0.61)
  Top 0.254: IC1.42 71.04,33.35 68.83,35.56 61.72,35.56 v61.47,35.81 | v38.48,39.24 38.73,39.37 IC6.12
  Bottom 0.254: v38.48,39.24 39.88,37.85 46.23,37.85 48.26,35.81 v61.47,35.81
GND  (via drill 0.61)
  Top 0.254: C12.2 19.34,66.25 19.3,66.29 19.27,66.25 | v14.86,11.56 14.92,11.62 | 47.62,37.12 47.62,37.09 IC11.9 | v24.13,8.89 23.37,8.38 23.37,6.48 23.24,6.35 23.24,3.3 23.11,3.05 22.1,3.05 22.19,2.96 C15.2 | 89.15,35.81 J7.22 | J7.19 91.14,33.83 | J7.24 89.15,37.85 | J7.26 89.17,39.86 89.15,39.88 | J7.28 89.17,41.89 89.15,41.91 | 89.15,43.94 89.17,43.93 J7.30 | 89.17,53.86 J7.40 89.15,53.85 | 76.49,8.04 76.58,7.87 76.58,8.13 76.49,8.04 | 76.49,8.04 C2.2 | IC2.1 56.39,58.17 | 69.49,40.23 IC3.14 70.36,40.39 | 12.95,21.08 12.99,21.05 J8.4 | 25.53,8.13 IC12.5 25.53,8.89 | 58.42,27.69 58.42,27.43 IC8.8 | 54.62,37.97 54.61,37.97 | 60.58,12.06 IC9.3 | 64.26,13.97 64.39,13.84 C23.1 64.27,13.97 64.26,13.97 | 61.09,10.54 C8.1 60.83,10.54 | IC9.8 v58.04,20.32 | 64.26,13.97 64.52,13.97 | 58.55,7.49 S1.4 58.55,7.47 58.55,7.49 | R5.3 78.62,65.67 78.61,65.66 77.22,65.66 v75.82,67.06 | C7.- 38.86,9.65 39.5,10.29 | v17.27,16.26 17.31,16.3 C20.1 17.31,17.87 17.21,17.97 R13.1 | 58.55,7.49 58.55,7.46 S1.4 | IC7.10 24.26,54.74 v23.88,55.12 | IC11.9 47.62,36.58 | IC11.9 | IC6.10 40.01,37.59 39.95,37.64 | D1.2 10.25,36.49 v10.67,36.96 11.18,37.47 C21.1 | IC10.3 58.55,9.27 | IC11.31 48.42,46.07 48.26,46.23 46.99,46.23 46.23,45.47 45.72,45.47 C22.1 | C28.- 40.51,50.29 42.16,51.94 v42.16,53.47 | 91.27,57.83 91.19,57.78 91.06,57.85 J7.43 91.27,57.83
  Top 0.305: v52.58,39.62 53.35,37.97 IC11.17 | 47.62,37.09 47.62,37.59
  Top 0.406: 14.92,11.62 IC4.15 14.92,19.11 12.99,21.05 | v23.88,49.66 IC7.6 | IC6.19 v29.84,47.88 | v54.61,46.74 IC2.10 | v52.58,39.62 52.64,39.56 50.8,39.56 48.51,39.55 47.62,37.59 | IC11.17 54.62,37.97 | C1.2 v74.3,8.13 76.58,8.13 | v57.91,59.18 57.91,58.17 IC2.1 | v67.51,40.23 69.49,40.23 | IC6.10 v40.01,39.12 | v24.13,8.89 25.53,8.89 | 58.42,27.69 59.69,28.96 59.69,34.67 59.05,35.31 54.86,35.31 54.61,35.56 54.61,37.97 | 60.58,12.06 60.83,11.68 60.83,10.54 60.83,9.27 58.55,9.27 | 58.55,9.27 55.63,9.27 D2.A | 58.55,9.27 58.55,7.49 | v74.17,59.69 C27.1 | C26.1 88.35,12.19 v85.98,12.19 | 22.35,36.43 C6.- 22.5,37.08 | C5.- 22.35,32.41 | 25.02,37.08 v25.15,37.34 | 39.5,10.29 v39.5,12.57 C25.1 | v60.96,21.97 60.96,23.37 58.42,25.91 58.42,27.43 | C24.1 6.44,10.25 5.71,9.53 J3.2 | IC7.18 v17.14,56.01 | IC7.27 16.89,44.58 v17.4,44.07 | IC7.21 v17.14,52.2 | IC7.25 16.51,47.12 v17.14,47.75 | C13.2 14.57,65.87 | 14.57,65.87 C11.2 | 14.57,65.87 14.48,66.17 | C11.2 v15.77,67.28 | 19.52,65.87 19.27,66.25 | C11.2 19.52,65.87 | 19.52,65.87 19.43,66.29 | v50.8,43.18 50.29,43.18 50.04,43.43 | IC11.29 50.02,43.45 50.04,43.43 | IC11.31 48.42,43.78 48.77,43.43 50.04,43.43
  Top 0.508: 72.64,16.94 IC1.16
  Top 0.559: 73.03,16.64 72.64,16.94
  Top 0.61: IC5.2 9.4,31.88 v10.16,31.37 | 91.14,33.83 89.15,35.81 | J7.22 J7.24 J7.26 J7.28 J7.30 | 89.17,43.93 87.88,45.21 87.88,52.58 89.15,53.85 | 50.8,39.56 v50.8,43.18 | 64.26,13.97 65.28,12.95 66.67,12.95 v66.74,13.02 66.8,13.08 | C29.- 2.54,35.43 v1.78,36.2
  Top 0.711: 73.03,16.64 73.03,11.43 74.42,10.03 81.66,10.03 C19.-
  Top 0.813: 22.35,32.41 22.35,36.43 | 22.5,37.08 25.02,37.08 | v66.74,9.02 v66.74,13.02 | C4.1 v31.5,53.21 C3.1 | 94.87,3.56 J5.2
  Top 1.27: D4.A 93.25,2.06 94.87,3.56
  Bottom 0.254: v54.61,46.74 56.44,48.56 IC2.1 v57.91,59.18 | v74.3,8.13 74.17,8.13 | 89.15,16 89.15,15.85 J7.2 | 91.14,57.83 91.06,57.91 | J7.43 91.14,57.83 | 91.14,57.83 91.19,57.78
  Bottom 0.406: v74.17,59.69 74.04,59.69
  pour Bottom (isolate 0.508): -1.02,-0.89 -1.02,70.23 100.08,69.98 100.08,-1.02
IR_IN  (via drill 0.61)
  Top 0.254: J4.1 46.99,2.67 47.88,1.78 52.32,1.78 55.37,4.83 59.56,4.83 62.36,7.62 67.56,7.62 68.71,8.76 v68.71,9.14 | v81.92,23.75 81.03,23.75 80.14,24.64 79.25,24.64 79.22,24.66 IC1.29
  Bottom 0.254: v68.71,9.14 68.83,9.14 68.83,9.27 77.22,9.27 83.69,15.88 83.69,22.23 v81.92,23.75
KEYS  (via drill 0.61)
  Top 0.254: 39.37,66.55 J2.15 | 39.37,66.55 40.64,65.28 40.64,63.5 41.4,62.74 42.16,62.74 44.83,60.96 46.23,60.96 47.24,59.94 48.26,59.94 50.8,57.4 50.8,51.56 53.59,48.77 53.59,46.35 54.23,45.72 63.75,45.72 v64.14,45.21 | IC1.9 67.69,21.59 v69.34,21.59 | R1.1 36.45,66.42 36.58,66.55 39.37,66.55
  Bottom 0.254: v64.14,45.21 63.75,45.21 63.75,41.91 67.94,37.72 67.94,33.53 69.6,31.88 69.6,28.57 68.83,27.81 68.83,26.8 70.36,25.27 70.36,22.35 v69.34,21.59
LCD_E  (via drill 0.61)
  Top 0.254: J2.6 52.07,63.5 55.12,60.45 58.29,60.45 64.26,54.36 v64.26,47.62 | IC1.26 74.35,22.3 70.48,26.16 69.47,26.16 68.83,26.8 68.83,28.45 67.94,29.34 v67.94,30.73 | IC6.9 38.73,37.59 v38.48,37.85
  Bottom 0.254: v67.94,30.73 67.94,32.51 67.31,33.15 67.31,34.8 | 67.31,34.8 67.31,37.59 63.12,41.78 63.12,47.12 63.63,47.62 v64.26,47.62 | v38.48,37.85 39.24,37.08 45.97,37.08 48.26,34.8 67.31,34.8
LCD_E3  (via drill 0.61)
  Top 0.254: v40.01,44.07 IC6.11
  Bottom 0.254: v40.01,44.07 41.27,45.34 41.27,50.55 45.09,54.36 45.08,55.49 J9.4
LCD_NEG
  Top 0.254: IC4.6 20,6.67 20.32,6.35 21.84,6.35 22.1,6.1 22.1,4.57 22.19,4.66 C15.1
MISO  (via drill 0.61)
  Top 0.254: IC1.2 66.42,27.05 65.38,28.09 65.38,28.6 v63.12,30.86 | v41.66,29.72 R9.1 | 32.38,23.62 32.38,16.38 30.86,14.86 30.86,7.24 J1.9 | v30.35,29.08 32.38,27.05 32.38,23.62 | 32.38,23.62 32.38,23.75
  Bottom 0.254: v63.12,30.86 62.74,31.24 46.61,31.24 45.09,29.72 v41.66,29.72 30.48,29.72 30.35,29.59 v30.35,29.08
MOSI  (via drill 0.61)
  Top 0.254: IC6.2 v29.84,31.62 29.84,31.11 33.02,27.94 33.02,16 31.5,14.48 31.5,8.38 34.29,5.59 34.29,1.91 35.05,1.14 43.69,1.14 44.58,2.03 44.58,3.68 J1.1 | v65.53,31.37 66.17,30.73 66.17,28.19 66.67,27.69 67.56,27.69 67.69,27.81 | 67.69,27.81 67.82,27.94 | 67.69,27.81 IC1.1
  Bottom 0.254: v29.84,31.62 45.21,31.62 46.1,32.51 64.39,32.51 v65.53,31.37
MOSI3  (via drill 0.61)
  Top 0.254: 27.18,45.85 IC7.3 | v22.48,47.24 21.97,47.62 21.97,57.91 22.61,58.55 IC7.13 26.54,58.55 26.9,58.98 43.66,58.98 45.09,57.53 45.07,57.52 J9.3 | IC6.18 31.11,43.94 29.21,42.04 27.94,42.04 27.56,42.42 27.56,45.47 27.18,45.85 | v27.18,47.24 27.18,45.85
  Bottom 0.254: v22.48,47.24 v27.18,47.24
MP3  (via drill 0.61)
  Top 0.254: v32.38,32.77 IC6.4 | v66.67,32.26 68.58,32.26 69.34,31.5 69.34,29.72 69.39,29.67 IC1.44
  Bottom 0.254: v32.38,32.77 33.02,32.38 44.96,32.38 45.72,33.15 64.9,33.15 66.04,32.26 v66.67,32.26
N$1  (via drill 0.61)
  Top 0.254: IC7.15 16.51,59.82 v18.03,61.34 | R8.2 21.91,64.33 21.72,64.26 v21.72,62.23
  Bottom 0.254: v18.03,61.34 19.3,61.34 20.19,62.23 v21.72,62.23
N$2
  Top 0.254: C11.1 17.06,64.56 17.02,64.52 17.27,64.26 17.27,63.5 19.05,61.72 19.05,51.56 18.54,50.93 IC7.22
N$3
  Top 0.254: IC7.24 14.48,48.39 13.97,47.88 13.97,43.94 12.22,42.19 12.22,39.9 11.18,39.5 C10.+
N$4
  Top 0.254: IC7.20 14.22,53.47 13.97,53.21 13.97,50.29 11.96,48.28 11.96,47.02 11.3,46.35 C9.+
N$5
  Top 0.254: 8.29,35.01 8.38,34.8 | 8.29,35.01 D1.1 | 6.1,34.8 R2.1 8.13,34.92 8.29,35.01
N$6
  Top 0.61: D2.K 55.63,18.29 | T1.D 45.21,15.32 45.21,17.4
  Top 0.813: 55.63,20.08 55.63,22.35 L3.P$1 | 55.63,20.08 55.63,20.19 48.01,20.19 45.21,17.4 | 55.63,20.08 D2.K
N$7
  Top 0.254: 70.87,8.17 71.12,8.13 | 70.87,8.17 C1.1 | Q1.2 70.99,5.71 70.99,8.13 | 70.99,8.13 70.87,8.17 | IC1.14 71.04,8.08 70.99,8.13
N$8
  Top 0.254: R11.2 2.35,48.32 3.56,50.04 11.18,50.04 12.45,51.31 12.37,51.38 J6.2
N$9
  Top 0.254: R11.1 2.35,46.16 2.54,45.97 4.83,45.97 6.03,46.29 6.04,46.29 | 6.04,46.29 6.1,46.23 | 6.04,46.29 C9.-
N$10
  Top 0.254: 78.11,7.83 C2.1 | Q1.1 78.11,4.32 78.11,7.83 | IC1.15 71.83,10.46 73.03,9.27 77.98,9.27 78.11,9.02 78.11,7.83
N$11
  Bottom 0.254: 0,0 0,68.9 99.2,68.9 99.2,0 0,0
N$12  (via drill 0.61)
  Top 0.254: IC4.14 16.22,14.19 16.26,14.22 v16.26,12.32 | v18.41,11.94 27.18,11.94 28.07,10.92 IC12.7
  Bottom 0.254: J3.1 3.81,11.94 4.57,12.7 15.75,12.7 v16.26,12.32 17.91,12.32 v18.41,11.94
N$13
  Top 0.254: IC7.8 26.29,52.2 26.54,52.45 27.94,52.45 28.19,52.7 28.19,53.72 28.57,54.1 29.34,54.1 R6.2 29.46,55.5 30.23,56.26 30.99,56.26 31.11,56.39 C4.2 34.94,56.48 Q2.2
N$14
  Top 0.254: IC7.7 26.16,50.93 26.67,51.44 28.07,51.44 28.45,51.82 29.34,51.82 29.43,51.98 | 29.43,51.98 29.43,52.03 29.34,52.2 R6.1 | 29.43,51.98 29.43,50.84 30.1,50.16 31.11,50.16 C3.2 32.3,50.08 33.4,51.18 34.92,51.18 Q2.1
N$15
  Top 0.254: 0,0 0,68.9 99.2,68.9 99.2,0 0,0
N$16  (via drill 0.61)
  Top 0.254: IC12.6 26.8,10.16 26.42,10.54 21.08,10.54 v20.57,10.03 18.54,10.03 17.4,11.18 17.4,13.97 17.53,14.1 17.46,14.16 IC4.13
  Bottom 0.254: v20.57,10.03 20.07,9.53 7.37,9.53 4.95,7.11 3.81,7.11 J3.3
N$17
  Top 0.254: R9.2 41.66,34.29 41.02,34.92 41.02,47.12 40.26,47.88 38.1,47.88 37.47,47.24 IC6.13
N$18
  Top 0.254: IC4.3 16.07,9.21 15.62,9.65 13.08,9.65 12.83,9.4 12.83,6.73 12.95,6.6 12.95,3.56 13.21,3.3 14.22,3.3 14.22,3.05 14.14,2.96 C16.2
N$19
  Top 0.254: R10.1 2.54,40.39 2.92,39.88 4.57,39.88 6.03,39.56 5.91,39.56 5.84,39.5 C10.-
N$20
  Top 0.254: IC4.5 18.73,6.92 19.56,6.1 19.56,4.57 19.65,4.66 C17.2
N$21
  Top 0.254: IC4.4 17.46,7.18 18.29,6.35 18.29,3.3 18.54,3.05 19.56,3.05 19.65,2.96 C17.1
N$22
  Top 0.254: IC4.2 14.92,6.92 15.49,6.35 16.51,6.35 16.76,6.1 C14.2
N$23
  Top 0.254: R10.2 2.6,42.86 1.14,44.7 1.14,49.78 2.29,50.93 4.19,50.93 6.6,53.34 6.6,56.26 10.79,60.45 10.85,60.4 J6.4
N$24
  Top 0.254: 53.34,34.92 53.35,34.92 | 53.34,34.92 IC8.13 | IC11.16 53.21,35.05 53.34,34.92
N$25
  Top 0.254: 52.07,34.42 52.04,34.45 | IC8.14 52.07,34.42 | 52.45,36.65 52.45,36.7 | 52.45,36.65 IC11.15 | 52.07,34.42 52.45,34.8 52.45,36.65
N$26
  Top 0.305: T1.G 52.32,12.98 52.32,14.99 53.21,15.88 58.8,15.88 59.31,16.38 IC9.7
N$27
  Top 0.305: J8.3 12.97,23.48 12.95,23.5 12.95,25.27 16.38,28.7 R18.2
N$28  (via drill 0.61)
  Top 0.254: R4.1 68.2,14.22
  Top 0.305: 60.58,18.41 IC9.6 v60.58,16.38
  Top 0.61: 51.18,17.4 51.28,17.4 T1.S
  Top 0.813: R4.1 R7.1 | 51.18,17.4 v51.18,15.49
  Bottom 0.61: R4.1 68.07,14.35
  Bottom 0.813: R4.1 66.29,16.38 v60.58,16.38 59.69,15.49 v51.18,15.49
N$29  (via drill 0.61)
  Top 0.254: 59.31,13.34 IC9.2 | 61.85,18.41 IC9.5 62.93,18.35 64.51,16.77 | 64.51,16.77 64.52,16.76 | 64.51,16.77 C23.2
  Top 0.406: IC9.5 61.85,16 61.21,15.24 59.94,15.24 59.31,14.48 59.31,13.34 59.31,10.92 v59.18,10.67
  Top 0.813: D3.1 90.9,11.4 89.79,10.29 84.71,10.29 C19.+ 81.79,11.56 R7.2 R4.2
  Bottom 0.406: v59.18,10.67 59.56,10.29 74.55,10.29 R7.2
N$30  (via drill 0.61)
  Top 0.254: 19.18,21.84 R14.1 | R13.2 19.18,19.88 19.18,21.84 | IC11.4 46.25,41.15 44.83,41.15 v43.94,42.04 | v20.95,23.37 20.95,22.86 19.94,21.84 19.18,21.84
  Bottom 0.254: v43.94,42.04 42.93,41.02 35.94,41.02 32.64,37.72 30.73,37.72 23.5,30.48 21.21,30.48 19.94,29.21 19.94,24.38 v20.95,23.37
N$31  (via drill 0.61)
  Top 0.254: v45.21,35.94 44.83,36.32 44.83,38.48 45.12,38.77 46.23,38.77 | R18.1 18.88,28.16 19.43,28.7 v22.86,28.7 22.86,26.29 21.84,25.27 17.65,25.27 17.21,24.83 R20.2 | 46.23,38.77 IC11.7 | 46.23,38.77 46.23,38.73
  Bottom 0.254: v45.21,35.94 44.7,36.45 31.37,36.45 23.62,28.7 v22.86,28.7
N$34
  Top 0.254: J8.1 15.39,20.98 16.26,21.84 R14.2 17.27,21.84
N$35
  Top 0.254: IC7.11 28.32,56.01 29.97,57.66 36.07,57.66 37.21,56.52 37.21,50.8 33.66,47.24 IC6.16 33.66,45.97
N$36
  Top 0.254: C21.2 14.82,37.05 12.64,34.86 L2.1 12.57,35.05 12.57,34.92 | R2.2 5.27,34.1 5.71,33.66 7.62,33.66 8.38,32.89 8.26,32.77 8.36,32.79 IC5.5 | L1.1 12.57,32
  Top 0.61: IC5.5 11.62,32.83 L1.1 12.57,32 12.57,34.92
N$37  (via drill 0.61)
  Top 0.254: IC7.4 24.77,47.12 23.24,45.59 v23.24,43.69 | v33.53,43.69 34.04,43.05 35.81,43.05 36.2,43.56 IC6.14
  Bottom 0.254: v23.24,43.69 23.62,44.07 33.15,44.07 v33.53,43.69
N$38
  Top 0.254: IC7.14 22.73,59.82 21.34,58.42 21.34,42.04 22.86,40.51 35.56,40.51 36.2,39.88 IC6.7
N$39
  Top 0.254: IC7.1 25.65,43.31 25.78,43.56 25.78,42.42 27.18,41.02 36.58,41.02 37.47,40.13 IC6.8
N$40  (via drill 0.61)
  Top 0.254: v46.23,34.8 46.22,36.69 46.23,36.69 46.23,37.97 IC11.8 | R19.1 18.76,26.33 19.05,26.04 19.18,26.54 v21.59,26.54
  Bottom 0.254: v46.23,34.8 44.96,34.8 44.07,35.69 31.5,35.69 22.35,26.54 v21.59,26.54
N$41
  Top 0.254: IC9.4 61.85,12.32 62.74,11.43 62.74,10.67 62.61,10.54 C8.2
N$42  (via drill 0.61)
  Top 0.254: v43.94,34.42 43.94,38.61 44.9,39.57 46.35,39.57 | v23.5,25.4 23.5,19.18 22.1,17.78 C20.2 | 46.35,39.57 IC11.6 | 46.35,39.57 46.35,39.62
  Bottom 0.254: v43.94,34.42 43.43,34.29 30.99,34.29 23.5,26.8 v23.5,25.4
N$43  (via drill 0.61)
  Top 0.254: R20.1 19.18,24.38 19.05,24.26 19.05,24.13 19.18,24.26 19.18,24.51 v22.35,24.51 | IC11.5 46.25,40.39 v43.94,40.39
  Bottom 0.254: v43.94,40.39 36.2,40.39 32.89,37.08 31.11,37.08 23.88,29.84 21.59,29.84 20.57,28.83 20.57,25.4 21.46,24.51 v22.35,24.51
N$44
  Top 0.254: 14.99,23.37 | J8.2 14.99,23.37 | R19.2 16.38,26.67 15.11,25.4 15.11,23.5 14.99,23.37
N$45
  Top 0.254: IC11.30 49.22,46.16 48.13,47.24 45.85,47.24 45.72,47.12 C22.2 44.79,47.2 44.58,46.99 44.58,45.72 44.32,45.47 43.56,45.47 43.43,45.59 R24.1
N$49
  Top 0.254: IC4.1 13.65,6.54 14.22,5.97 14.22,4.57 14.14,4.66 C16.1
N$50
  Top 0.254: R15.1 39.56,33.21 39.62,33.15 D5.1
N$53  (via drill 0.61)
  Top 0.254: 35.49,11.12 v35.43,11.18 | J4.3 52.07,5.21 50.93,6.6 48.77,6.6 45.72,9.65 v44.96,9.65 42.8,9.65 42.76,9.69
  Top 0.305: R3.1 35.56,9.53 35.49,9.84 35.49,11.12 | C7.+ 42.55,9.65 42.76,9.69
  Bottom 0.254: v35.43,11.18 35.43,10.54 36.32,9.65 v44.96,9.65
N$54
  Top 0.254: IC11.27 51.62,48.71 50.16,50.16 Q3.1
N$55
  Top 0.254: IC11.28 50.82,47.61 49.4,49.02 45.72,49.02 Q3.3
RD  (via drill 0.61)
  Top 0.254: v72.39,49.28 IC3.22 | IC1.13 70.21,18.03 70.23,18.1 70.23,18.86 v71.37,20.07 | IC8.1 v49.53,30.23
  Bottom 0.254: v72.39,49.28 70.61,49.28 69.6,48.26 69.6,40.39 71.37,38.61 v71.37,20.07 70.36,19.05 68.96,19.05 67.82,20.19 67.82,23.75 67.06,24.51 67.06,28.45 66.29,29.21 50.55,29.21 v49.53,30.23
RST  (via drill 0.61)
  Top 0.254: IC1.4 67.56,25.4 69.34,25.4 | R12.1 36.32,13.08 37.08,12.32 37.08,8.64 37.34,8.38 38.1,8.38 | IC6.5 33.66,33.15 36.2,30.61 | R12.1 | v85.34,18.8 78.49,18.8 77.72,19.56 77.72,21.72 73.53,21.72 69.85,25.4 69.34,25.4 | v69.34,24.64 69.34,25.4 | 38.1,8.38 40.39,8.38 40.61,8.61 40.61,10.51 40.89,10.79 45.59,10.79 49.02,7.37 52.45,7.37 | J1.5 38.1,8.38 | S1.2 55.5,7.37 52.45,7.37 | 36.2,30.61 36.2,14.73 35.56,14.1 R12.1 | 36.2,30.73 v35.94,30.67 36.2,30.61 | IC10.1 52.45,8.28 52.45,7.37
  Bottom 0.254: J7.1 91.17,16.02 90.42,16.83 87.88,16.83 85.72,18.8 v85.34,18.8 | v35.94,30.67 36.13,30.67 36.2,30.73 45.21,30.73 46.35,31.88 63.63,31.88 65.02,30.48 66.8,30.48 68.2,29.08 68.2,25.78 v69.34,24.64
RST3  (via drill 0.61)
  Top 0.254: IC7.26 v17.78,45.85 | v34.92,44.2 IC6.15
  Bottom 0.254: v17.78,45.85 18.29,45.85 19.43,44.7 34.42,44.7 v34.92,44.2 37.59,46.86 37.59,52.45 41.02,55.88 | 41.02,55.88 J9.8 | 41.02,55.88
RX  (via drill 0.61)
  Top 0.254: 24.38,12.57 24.38,24.64 v25.4,25.78 | IC1.5 67.59,24.66 67.56,24.64 66.42,24.64 v64.39,26.67 | 24.38,12.57 19.3,12.57 18.92,12.95 18.92,14.1 18.76,14.19 | 18.76,14.19 IC4.12 | 18.76,14.19 18.8,14.22 | IC12.1 29.34,12.95 28.96,12.57 24.38,12.57
  Bottom 0.254: v25.4,25.78 27.43,27.94 63.12,27.94 v64.39,26.67
RXF  (via drill 0.61)
  Top 0.254: IC1.11 65.79,19.94 60.07,25.78 v60.07,26.29 | v48.01,26.29 47.5,26.92 47.5,34.29 48.26,35.05 49.53,35.05 | 49.53,35.05 49.52,35.04 | IC11.12 50.04,36.6 50.04,35.56 49.53,35.05
  Bottom 0.254: v48.01,26.29 v60.07,26.29
SCF  (via drill 0.61)
  Top 0.254: 33.02,62.48 33.02,62.23 33.27,61.98 | 33.27,61.98 33.27,61.59 34.29,60.58 40.89,60.58 v41.15,60.71 | 33.27,61.98 D6.2
  Top 0.305: 33.02,62.48 R16.2
  Bottom 0.254: v41.15,60.71 43.07,58.66 J9.5
SCK  (via drill 0.61)
  Top 0.254: IC6.3 31.11,32 33.66,29.46 v33.66,28.83 33.66,15.62 32.26,14.22 32.26,8.38 J1.7 | IC1.3 67.61,26.36 67.56,26.16 66.42,26.16 v64.39,28.19
  Bottom 0.254: v33.66,28.83 34.42,28.57 64.01,28.57 v64.39,28.19
SCK3
  Top 0.254: 32.38,46.1 IC6.17 32.38,44.45 29.46,41.53 27.69,41.53 26.8,42.42 26.8,43.94 26.16,44.58 IC7.2 24.77,44.58 24.26,44.07 24.26,43.18 23.75,42.67 22.86,42.67 22.1,43.43 22.1,45.34 23.5,46.74 23.5,48.01 22.61,48.9 22.61,56.64 23.24,57.28 IC7.12 26.8,57.28 27.89,58.47 41.5,58.47 42.06,57.91 42.09,56.84 42.47,56.46 46.28,56.46 46.99,55.75 46.99,55.49 J9.2
TX  (via drill 0.61)
  Top 0.254: IC1.7 67.74,23.04 67.56,23.11 66.29,23.11 v62.74,26.67 | IC12.4 25.4,16 v25.4,17.02 26.54,18.16 26.54,25.65 v28.07,27.05 | 20.07,14.1 20,14.16 IC4.11 20,15.68 21.34,17.02 v23.24,17.02
  Bottom 0.254: v28.07,27.05 28.32,27.3 62.1,27.3 v62.74,26.67 | v23.24,17.02 v25.4,17.02
TX_ENABLE  (via drill 0.61)
  Top 0.254: IC12.2 26.82,15.01 26.8,14.22 | IC1.8 66.22,22.3 v66.04,22.1 | v42.93,26.29 42.93,28.57 | 42.93,28.57 42.93,34.29 41.66,35.56 41.66,50.29 44.07,52.7 46.48,52.7 49.02,55.24 49.02,58.29 48.01,59.31 46.99,59.31 45.97,60.33 44.7,60.33 42.29,61.98 39.37,61.98 | 39.37,61.98 J2.16 | IC12.3 26.8,14.22 | 26.8,14.22 26.8,14.1 | 26.8,14.22 26.67,14.35 | v31.37,26.29 29.08,26.29 27.69,24.89 27.69,16.51 28.07,16.13 IC12.2 | IC12.2 28.07,14.22 | D5.2 39.75,29.72 40.89,28.57 42.93,28.57 | 39.37,61.98 D6.1
  Bottom 0.254: v66.04,22.1 65.79,22.1 62.74,25.27 44.07,25.27 v42.93,26.29 v31.37,26.29
TXE  (via drill 0.61)
  Top 0.254: v56.01,36.83 56.52,36.2 59.82,36.2 60.45,35.69 60.45,28.96 61.34,28.07 61.34,25.27 65.91,20.7 67.56,20.7 67.61,20.75 | 67.61,20.75 67.69,20.83 | 67.61,20.75 IC1.10 | IC11.14 51.62,38.16 v51.82,38.35
  Bottom 0.254: v56.01,36.83 53.34,36.83 v51.82,38.35
VCC  (via drill 0.61)
  Top 0.254: C14.1 16.76,2.29 16,1.52 12.95,1.52 12.45,2.03 12.45,6.22 12.32,6.35 12.32,8.51 | 12.32,8.51 12.32,9.65 12.45,9.91 13.46,10.92 13.46,13.72 13.72,13.97 13.65,14.03 IC4.16 | 80.26,56.9 IC3.28 | 52.39,44.01 52.42,44.99 IC11.26 | 49.21,36.77 49.22,36.65 49.15,36.65 49.15,36.62 | R12.2 33.59,12.89 | 91.19,55.88 91.17,55.86 J7.41 | 74.17,28.68 74.17,28.83 | IC11.13 50.82,36.74 50.8,36.74 50.8,36.62 | IC11.13 50.82,35.45 50.8,35.43 49.66,34.42 IC8.16 | 53.59,14.73 53.72,14.86 | L3.P$2 38.1,22.48 | L3.P$2 | IC12.8 29.34,10.79 30.23,11.68 30.23,15.24 31.75,16.76 31.75,21.59 C18.+ | 78.74,63.37 78.73,63.37 R5.1 78.65,61.63 77.98,60.96 77.98,59.69 C27.2 | C24.2 12.23,8.55 12.32,8.51 | 41.15,16.13 40.98,16.09 | 49.15,36.62 49.15,36.58 | 49.15,36.62 IC11.11 | 50.8,36.62 50.8,36.58 | IC11.13 50.8,36.62 | IC10.2 52.32,10.3 52.32,11.43 | L3.P$2 38.23,29.84 37.72,30.35 R15.2 | R24.2 43.43,48.01 43.94,48.51 48.26,48.51 v49.78,46.99
  Top 0.406: IC4.16 13.65,18.1 v13.59,18.41 | 66.5,58.22 66.55,58.17 IC2.20 | v49.59,41.66 49.59,41.71 49.22,41.97 IC11.3 | v52.39,42.29 52.39,44.01 | 49.21,36.77 v49.21,38.35 49.28,38.35 49.4,38.23 50.55,38.23 50.82,37.95 50.82,36.74 | 33.59,12.89 R3.2 33.59,9.59 | J1.2 41.91,3.81 37.34,3.81 36.83,4.32 36.83,6.1 36.07,6.86 34.8,6.86 33.78,7.87 33.78,9.4 33.59,9.59 | 33.59,9.59 33.53,9.65 | v34.8,24.38 34.8,15.24 33.66,14.1 R12.2 | 57.15,64.01 J2.2 | R1.2 36,64.58 v34.92,65.66 | IC9.1 58.04,14.48 57.66,14.86 53.72,14.86 | 53.59,14.73 53.59,11.94 53.09,11.43 52.32,11.43 41.15,11.43 41.15,16.13 41.15,17.78 38.23,20.7 L3.P$2 | C27.2 77.98,59.65 77.98,58.17 | 88.39,14.22 C26.2 | 40.98,16.09 C25.2
  Top 0.508: 74.17,28.68 IC1.38
  Top 0.61: IC5.1 4.76,32.83 4.45,32.38 4.45,31.37 | 4.45,31.37 4.89,30.92 IC5.3 5.38,30.73 | 74.17,28.68 74.17,27.69 v75.06,27.43 | C29.+ 4.32,31.49 4.45,31.37
  Top 0.813: 5.38,30.73 5.33,30.48 5.33,25.78 12.7,18.41 v13.59,18.41 | 66.5,58.22 63.96,58.22 v61.59,60.58 58.17,64.01 57.15,64.01 | IC2.20 77.98,58.17 78.99,58.17 80.26,56.9 88.14,56.9 89.17,55.86 J7.42 | 91.19,55.88 94.23,55.88 96.01,54.1 96.01,17.78 92.46,14.22 88.39,14.22 v78.61,14.22
  Bottom 0.254: 89.2,55.83 89.17,55.86 J7.42 | 57.15,64.01 J2.2 57.28,64.01 | 35.18,65.41 v34.92,65.66 | 49.28,38.35 49.15,38.48 | 52.45,46.99 v49.78,46.99
  Bottom 0.406: 52.45,42.35 v52.39,42.29 | 35.18,65.41 55.75,65.41 J2.2
  Bottom 0.61: 34.92,24.26 v34.8,24.38 | L3.P$2
  Bottom 0.813: v52.39,42.29 52.39,42.23 52.32,41.66 v49.59,41.66 49.59,40.32 49.28,40.01 49.28,38.35 v49.21,38.35 | J7.41 89.2,55.83 | 75.06,17.02 v75.06,27.43 | 75.06,17.02 76.2,17.02 77.85,14.22 v78.61,14.22 | 52.45,42.35 52.45,46.99 52.45,47.62 55.5,50.42 55.5,59.44 56.64,60.58 v61.59,60.58 | v13.59,18.41 17.78,18.41 20.07,20.57 26.16,20.57 C18.+ | C18.+ 29.84,24.26 34.92,24.26 38.23,24.26 | 75.06,17.02 67.82,17.02 60.58,24.26 38.23,24.26 | 38.23,24.26 L3.P$2 | C18.+ 30.1,24.13
VCC/2  (via drill 0.61)
  Top 0.406: C13.1 14.61,63.63 13.97,62.99 13.97,54.99 14.22,54.74 | C6.+ 18.92,37.72 19.3,37.59
  Top 0.61: IC7.19 14.22,54.74 v12.57,54.74 | IC7.23 v17.02,49.66 19.3,49.66 19.3,37.59 | L2.2 15.43,34.92 15.49,34.92 17.89,36.81 C6.+
  Bottom 0.61: v17.02,49.66 v12.57,54.74
VDD  (via drill 0.61)
  Top 0.254: 21.78,65.97 R8.1 | IC7.5 25.4,48.39 | v28.57,43.05 IC6.20 | 26.29,53.47 IC7.9 | R16.1 31.94,66.48 31.75,66.29 31.75,61.59 31.37,61.09 31.11,60.96
  Top 0.305: C12.1 19.34,64.56 19.3,64.52 20.07,64.52 20.57,65.02 20.57,65.41 21.02,65.97 21.78,65.97
  Top 0.406: 28.57,37.97 IC6.1 | L1.2 15.37,32.51 | 20.57,60.96 31.11,60.96 | 31.11,60.96 31.24,60.96 | 31.11,60.96 32.08,59.61 44.91,59.61 46.61,57.91 47.08,57.49 J9.1
  Top 0.61: 27.18,48.39 v27.18,50.55 | 27.18,48.39 IC7.5 | 27.18,48.39 28.57,48.39 IC6.20 v28.57,43.05 | v28.57,39.62 28.57,37.97 28.57,33.78 25.65,30.86 19.92,30.86 C5.+ 15.37,32.51 | v27.18,53.47 26.29,53.47 | v15.24,39.62 IC7.28 | v20.57,39.62 20.57,60.96 20.57,61.85 19.3,63.12 19.3,64.52
  Bottom 0.61: v27.18,50.55 v27.18,53.47 | v15.24,39.62 v20.57,39.62 v28.57,39.62 v28.57,43.05
VO
  Top 0.254: J2.3 54.61,66.29 55.63,65.28 58.67,65.28 64.01,59.94 71.63,59.94 73.28,61.59 73.28,64.52 R5.2
VOUT
  Top 0.254: J9.7 40.98,57.49 39.88,56.39 39.88,53.47 40.13,53.21 C28.+
WR  (via drill 0.61)
  Top 0.254: IC3.27 78.49,55.63 77.98,55.12 v77.98,50.55 | 69.39,18.09 69.34,18.03 | 69.39,18.09 IC1.12 | v69.6,20.07 69.6,18.29 69.39,18.09 | IC8.2 50.8,29.84 v51.44,30.23
  Bottom 0.254: v77.98,50.55 70.36,50.55 69.09,49.28 69.09,40.01 70.87,38.23 70.87,21.08 v69.6,20.07 69.09,20.07 68.45,20.7 68.45,23.88 67.69,24.64 67.69,28.7 66.55,29.84 51.82,29.84 v51.44,30.23

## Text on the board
Top: Rev. C | 020412
Bottom: www.yampp.com | yampp-3/USB
tPlace: 1 | www.yampp.com | V+ | GND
